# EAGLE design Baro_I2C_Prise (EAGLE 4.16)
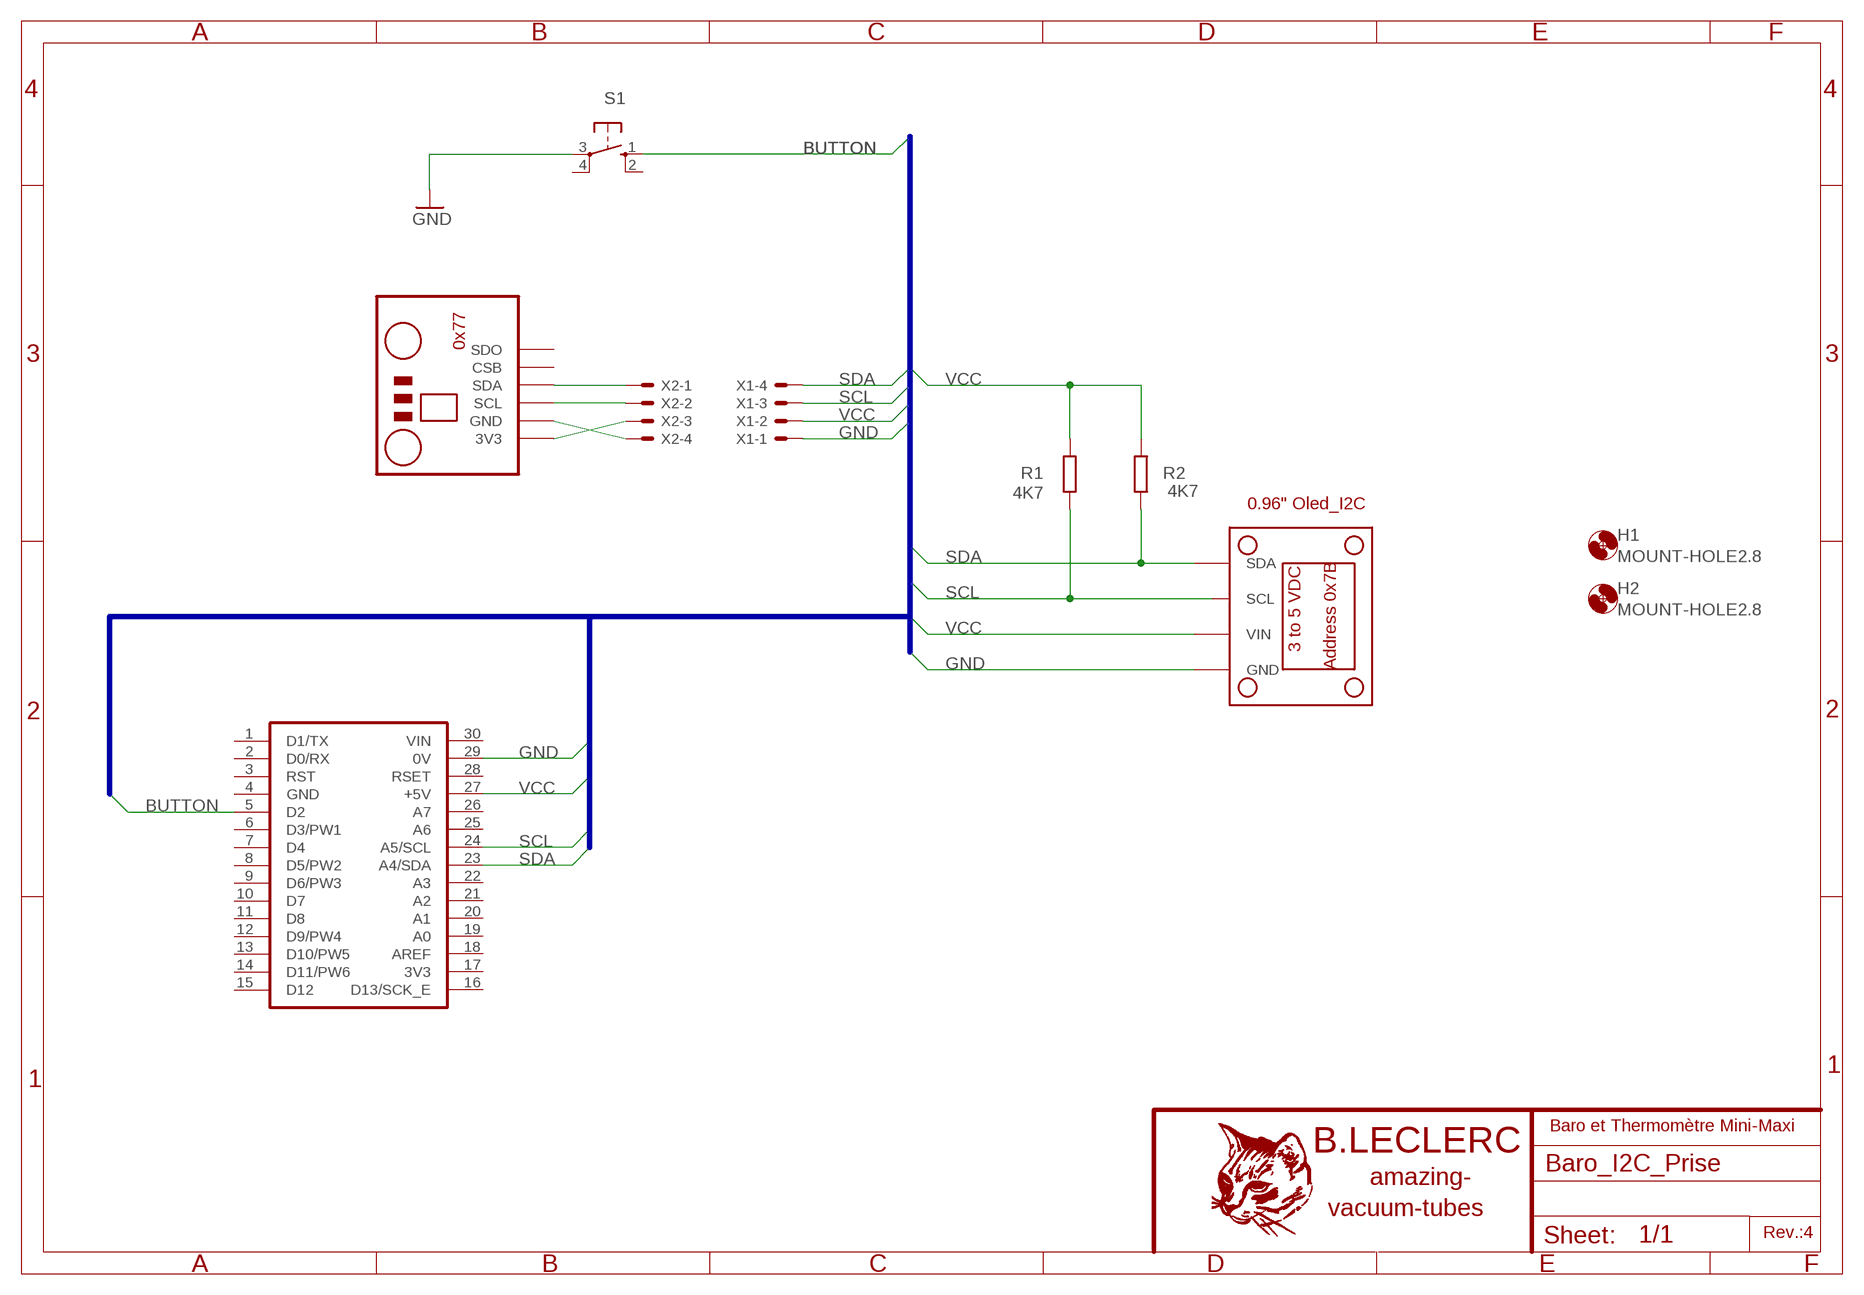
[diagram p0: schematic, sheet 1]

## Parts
H1  MOUNT-HOLE2.8  [2,8]
H2  MOUNT-HOLE2.8  [2,8]
R1  4K7  R-EU_M1206  [M1206]
R2  4K7  R-EU_M1206  [M1206]
S1  10-XX  [B3F-10XX]
U1  NANO  [NANO]
U$2  OLED_I2C_DISPLAY  [OLED_I2C_DISPLAY]
U$3  BMP280  [BMP280]
X1  22-23-2041  [22-23-2041]
X2  22-23-2041  [22-23-2041]

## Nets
BUTTON: S1.1(S) U1.5(D2)
GND: S1.3(P) U1.29(0V) U$2.GND X1.1
N$1: U$3.SDA X2.1
N$7: U$3.SCL X2.2
N$8: U$3.3V3 X2.3
N$9: U$3.GND X2.4
SCL: R1.1 U1.24(A5/SCL) U$2.SCL X1.3
SDA: R2.1 U1.23(A4/SDA) U$2.SDA X1.4
VCC: R1.2 R2.2 U1.27(+5V) U$2.VIN X1.2
Unconnected: S1.2(S1) S1.4(P1) U1.1(D1/TX) U1.2(D0/RX) U1.3(RST) U1.6(D3/PW1) U1.7(D4) U1.8(D5/PW2) U1.9(D6/PW3) U1.10(D7) U1.11(D8) U1.12(D9/PW4) U1.13(D10/PW5) U1.14(D11/PW6) U1.15(D12) U1.16(D13/SCK_E) U1.18(AREF) U1.19(A0) U1.20(A1) U1.21(A2) U1.22(A3) U1.25(A6) U1.26(A7) U1.28(RSET) U$3.CSB U$3.SDO

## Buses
B$1

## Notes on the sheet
- Baro et Thermomètre Mini-Maxi
- Rev.:4

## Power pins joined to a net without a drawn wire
3V3: U1.17(3V3)
GND: U1.4(GND)
VIN: U1.30(VIN)

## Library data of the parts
H1 H2 = holes:MOUNT-HOLE: MOUNTING HOLE with drill center marker
R1 R2 = rcl:R-EU_: RESISTOR, European symbol
S1 = switch-omron:10-XX: OMRON SWITCH
U1 = Arduino:NANO
U$2 = Arduino:OLED_I2C_DISPLAY
U$3 = Arduino:BMP280
X1 X2 = con-molex:22-23-2041: .100" (2.54mm) Center Header - 4 Pin

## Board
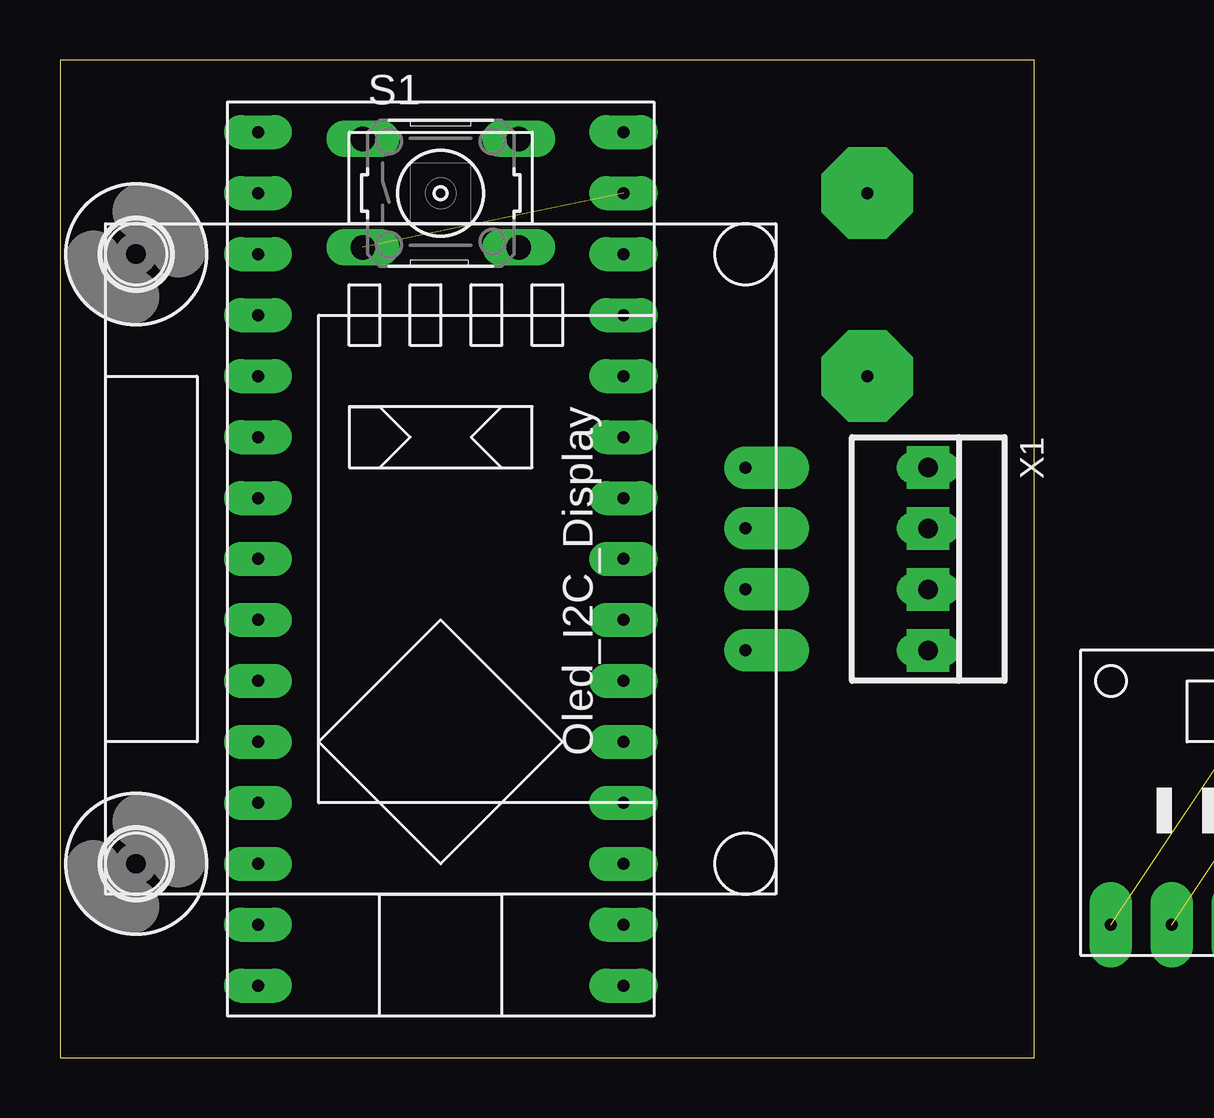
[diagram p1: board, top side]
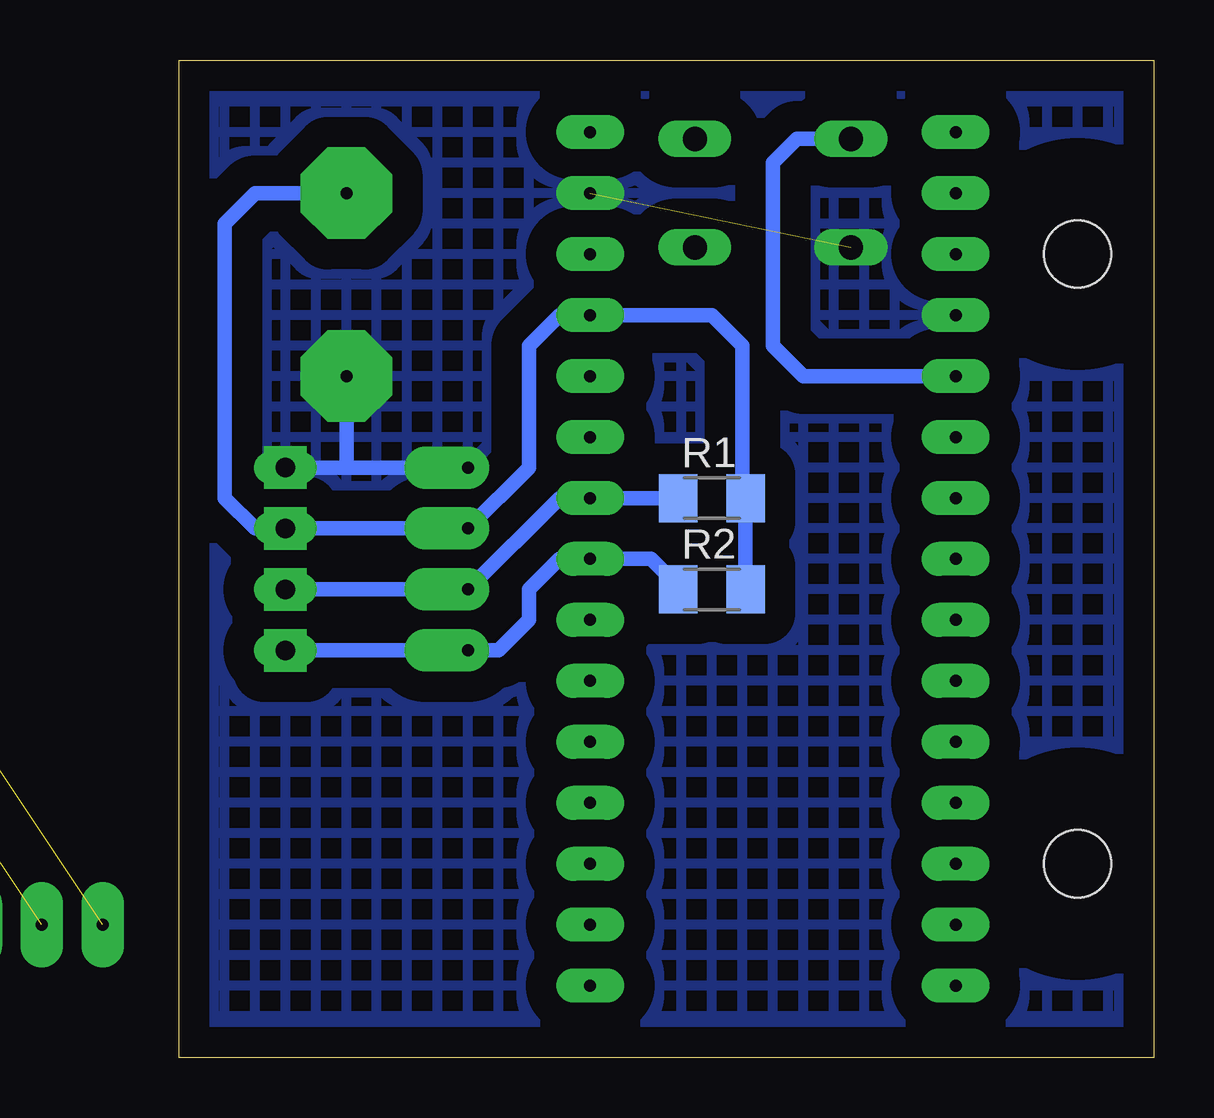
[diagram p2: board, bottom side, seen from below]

Size 40.62 x 41.58 mm. Coordinates in mm from the lower left corner, seen from the top.
Outline: 0,0 40.62,0 40.62,41.58 0,41.58 0,0
Copper layers (1*16): Top 0.035mm / dielectric 1.5mm / Bottom 0.035mm
Design rules "default": minimum track width 10mil, minimum drill 24mil, track to track 8mil, track to pad 8mil, pad to pad 8mil, via to via 8mil, smd to smd 8mil, copper to edge 40mil, drill to drill 8mil, minimum pad ring 10mil, minimum via ring 8mil, stop-mask expansion 4mil, vias tented up to drill 0mil, thermal gap 10mil

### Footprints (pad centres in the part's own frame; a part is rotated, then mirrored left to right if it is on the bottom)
2,8 = hole 2.8: 0,0
M1206 = smd 1.6 x 2: 1 -1.4,0; 2 1.4,0
B3F-10XX = drill 1.016 long: 1 -3.251,2.261; 2 3.251,2.261; 3 -3.251,-2.261; 4 3.251,-2.261
NANO = drill 0.5 pad 1.422 long: 1 -7.62,17.78; 2 -7.62,15.24; 3 -7.62,12.7; 4 -7.62,10.16; 5 -7.62,7.62; 6 -7.62,5.08; 7 -7.62,2.54; 8 -7.62,0; 9 -7.62,-2.54; 10 -7.62,-5.08; 11 -7.62,-7.62; 12 -7.62,-10.16; 13 -7.62,-12.7; 14 -7.62,-15.24; 15 -7.62,-17.78; 16 7.62,-17.78; 17 7.62,-15.24; 18 7.62,-12.7; 19 7.62,-10.16; 20 7.62,-7.62; 21 7.62,-5.08; 22 7.62,-2.54; 23 7.62,0; 24 7.62,2.54; 25 7.62,5.08; 26 7.62,7.62; 27 7.62,10.16; 28 7.62,12.7; 29 7.62,15.24; 30 7.62,17.78
OLED_I2C_DISPLAY = drill 0.5 pad 1.778 offset: GND 10.16,26.67; SCL 15.24,26.67; SDA 17.78,26.67; VIN 12.7,26.67
BMP280 = drill 0.5 pad 1.778 long: 3V3 -6.35,-7.62; CSB 3.81,-7.62; GND -3.81,-7.62; SCL -1.27,-7.62; SDA 1.27,-7.62; SDO 6.35,-7.62
22-23-2041 = drill 0.813 long: 1 -3.81,0; 2 -1.27,0; 3 1.27,0; 4 3.81,0

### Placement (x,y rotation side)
H1  3.17,33.49 0 top
H2  3.17,8.09 0 top
R1  18.41,23.33 0 bottom
R2  18.41,19.52 0 bottom
S1  15.87,36.03 0 top
U1  15.87,20.79 0 top
U$2  1.9,34.76 270 top
U$3  not placed on the board
X1  36.19,20.79 270 top
X2  not placed on the board

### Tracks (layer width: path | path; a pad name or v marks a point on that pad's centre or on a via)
BUTTON
  Bottom 0.61: S1.1 14.88,38.29 15.87,37.3 15.87,29.68 14.6,28.41 U1.5
GND  (via drill 0.5 pad 1.78, 0.5 pad 3.81)  (1 unrouted)
  Bottom 0.61: U$2.GND 33.65,24.6 | 33.65,24.6 X1.1 | 33.65,24.6 v33.65,28.41
  other vias: 36.19,24.6
  pour Bottom (isolate 1.27, no thermals, hatched): 0.63,41.11 40,41.11 40,0.47 0.63,0.47
N$1  (1 unrouted)
N$3  (via drill 0.5 pad 1.78)
  other vias: 36.19,22.06
N$4  (via drill 0.5 pad 1.78)
  other vias: 36.19,19.52
N$5  (via drill 0.5 pad 1.78)
  other vias: 36.19,16.98
N$7  (1 unrouted)
N$8  (1 unrouted)
N$9  (1 unrouted)
SCL
  Bottom 0.61: R1.1 U1.24 24.76,23.33 U$2.SCL X1.3
SDA
  Bottom 0.61: R2.1 19.68,19.52 20.95,20.79 U1.23 24.76,20.79 26.03,19.52 26.03,18.25 27.3,16.98 U$2.SDA X1.4
VCC  (via drill 0.5 pad 3.81)
  Bottom 0.61: R2.2 17.14,19.52 17.01,19.65 R1.2 17.14,23.33 17.14,29.68 18.41,30.95 U1.27 24.76,30.95 26.03,29.68 26.03,24.6 U$2.VIN X1.2 37.46,22.06 38.73,23.33 38.73,34.76 37.46,36.03 v33.65,36.03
